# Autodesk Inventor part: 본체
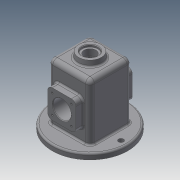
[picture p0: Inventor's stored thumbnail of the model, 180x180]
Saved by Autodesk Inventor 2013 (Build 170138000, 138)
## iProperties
Created: 2021-08
Part Number: 본체
Material: 일반
Document SubType Name: Modeling
Designer: a
Density: 1 g/cm^3
Mass: 304.335 g
Surface Area: 949.017 cm^2
Volume: 304.335 cm^3
Author: a
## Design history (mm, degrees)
sketch "스케치1"
  geometry: L1 (-37, -37)-(37, -37); L2 (37, -37)-(37, 37); L3 (37, 37)-(-37, 37); L4 (-37, 37)-(-37, -37); L5 (-37, -37)-(37, 37); L6 (37, -37)-(-37, 37); 1 further point
  constraints: 12 end point, 2 midpoint, 2 parallel, 1 horizontal, 1 perpendicular
  dimensions: "d0" = 74 distance of L3.end L2.end; "d1" = 74 distance of L2.end L1.end
extrude "돌출1" new body sketch "스케치1" distance "d2" = 110; taper "d3" = 0 deg
feature "쉘1" dims "d4" = 5
sketch "스케치2"
  geometry: L1 (37, -37)-(-37, -37) reference; L2 (37, 37)-(37, -37) reference; L3 (-37, 37)-(37, 37) reference; L4 (-37, -37)-(-37, 37) reference; C1 r 67 at (0, 0); 1 further point
  constraints: 1 centre point, 1 coincident
  dimensions: "d5" = 134 diameter of C1
extrude "돌출2" join sketch "스케치2" distance "d6" = 10; taper "d7" = 0 deg
sketch "스케치3"
  geometry: L1 (104, -110)-(-30, -110) reference; L2 (12, -80)-(62, -80); L3 (62, -80)-(62, -30); L4 (62, -30)-(12, -30); L5 (12, -30)-(12, -80); L6 (12, -80)-(62, -30); L7 (62, -80)-(12, -30); 4 further points
  constraints: 12 end point, 4 midpoint, 2 parallel, 1 horizontal, 1 perpendicular, 1 vertical alignment
  dimensions: "d8" = 50 distance of L4.end L3.end; "d9" = 50 distance of L3.end L2.end; "d10" = 55 distance of point (37, -110) point (37, -55)
extrude "돌출3" join sketch "스케치3" distance "d11" = 13; taper "d12" = 0 deg
node "작업 평면1"
sketch "스케치6"
  geometry: C1 r 20 at (0, 0); 1 further point
  constraints: 1 centre point, 1 coincident
  dimensions: "d21" = 40 diameter of C1
extrude "돌출6" join sketch "스케치6" stored distance "d22" = 7; taper "d23" = 6 deg
sketch "스케치7"
  geometry: C1 r 20 at (0, 0) reference; 1 further point
  constraints: 1 coincident
hole "구멍1" sketch "스케치7" at (0, 0) diameter "d24" = 21; stored, may be unused: countersink angle "d28" = 90 deg, drill point angle "d30" = 0 deg; dims "d25" = 6, "d26" = 28, "d27" = 4, "d29" = 8
sketch "스케치10"
  geometry: L1 (37, 37)-(-37, 37) reference; L2 (0, 0)-(-55, 0); L3 (-55, 0)-(55, 0); C1 r 67 at (0, 0) reference; C2 r 4.5 at (-55, 0); C3 r 4.5 at (55, 0)
  constraints: 4 end point, 2 centre point, 2 coincident, 1 collinear, 1 parallel
  dimensions: "d46" = 55 distance of L2.start L2.end; "d47" = 110 distance of L2.end L3.end; "d48" = 9 diameter of C2; "d49" = 9 diameter of C3
extrude "돌출8" cut sketch "스케치10" stored distance "d50" = 7; taper "d51" = 0 deg
fillet "모깎기1" dims "d52" = 8
fillet "모깎기2" dims "d53" = 8
fillet "모깎기3" dims "d54" = 3
fillet "모깎기4" dims "d55" = 3
fillet "모깎기5" dims "d56" = 3
fillet "모깎기6" dims "d57" = 3
fillet "모깎기7" dims "d58" = 8
fillet "모깎기8" dims "d59" = 3
chamfer "모따기1" distance "d60" = 1; stored, may be unused: second distance "d61" = 2, angle "d62" = 45 deg
sketch "스케치11"
  geometry: L1 (58, 102)-(58, 0) reference; L2 (29, 0)-(29, 55); C1 r 25 at (29, 55)
  constraints: 2 end point, 1 centre point, 1 coincident, 1 parallel
  dimensions: "d63" = 55 distance of L2.start L2.end; "d64" = 50 diameter of C1
extrude "돌출9" join sketch "스케치11" distance "d65" = 7; taper "d66" = -20 deg
sketch "스케치12"
  geometry: L1 (12, -38)-(12, -72) reference; L2 (37, -110)-(37, -55); C1 r 16 at (37, -55)
  constraints: 2 end point, 1 centre point, 1 coincident, 1 parallel
  dimensions: "d67" = 55 distance of L2.start L2.end; "d68" = 32 diameter of C1
extrude "돌출10" cut sketch "스케치12" stored distance "d69" = 7; taper "d70" = 0 deg
sketch "스케치13"
  geometry: A1 r 8 centre (20, -72) between (12, -72) and (20, -80) reference; A2 r 8 centre (54, -72) between (54, -80) and (62, -72) reference; A3 r 8 centre (54, -38) between (62, -38) and (54, -30) reference; A4 r 8 centre (20, -38) between (20, -30) and (12, -38) reference; 5 further points
  constraints: 4 coincident
hole "구멍3" sketch "스케치13" at (20, -38), (20, -72), (54, -72), (54, -38) diameter "d71" = 3.242; stored, may be unused: countersink angle "d75" = 90 deg, drill point angle "d77" = 118 deg; dims "d72" = 8, "d73" = 28, "d74" = 4, "d76" = 10
sketch "스케치14"
  geometry: L1 (9, 18)-(49, 18) reference; L2 (-8, 0)-(-8, -89) reference; 2 further points
  constraints: 1 other
  dimensions: "d78" = 28 distance from line of point (29, -10) L1; "d79" = 37 distance from line of L2 point (29, -10)
feature "엠보싱1" sketch "스케치14" dims "d0" = 74, "d1" = 74, "d80" = 0.5, "d81" = 0
chamfer "모따기2" distance "d82" = 1; stored, may be unused: second distance "d83" = 2, angle "d84" = 45 deg
node "솔리드1"
mirror "대칭1"
mirror "대칭4"
mirror "대칭5"
